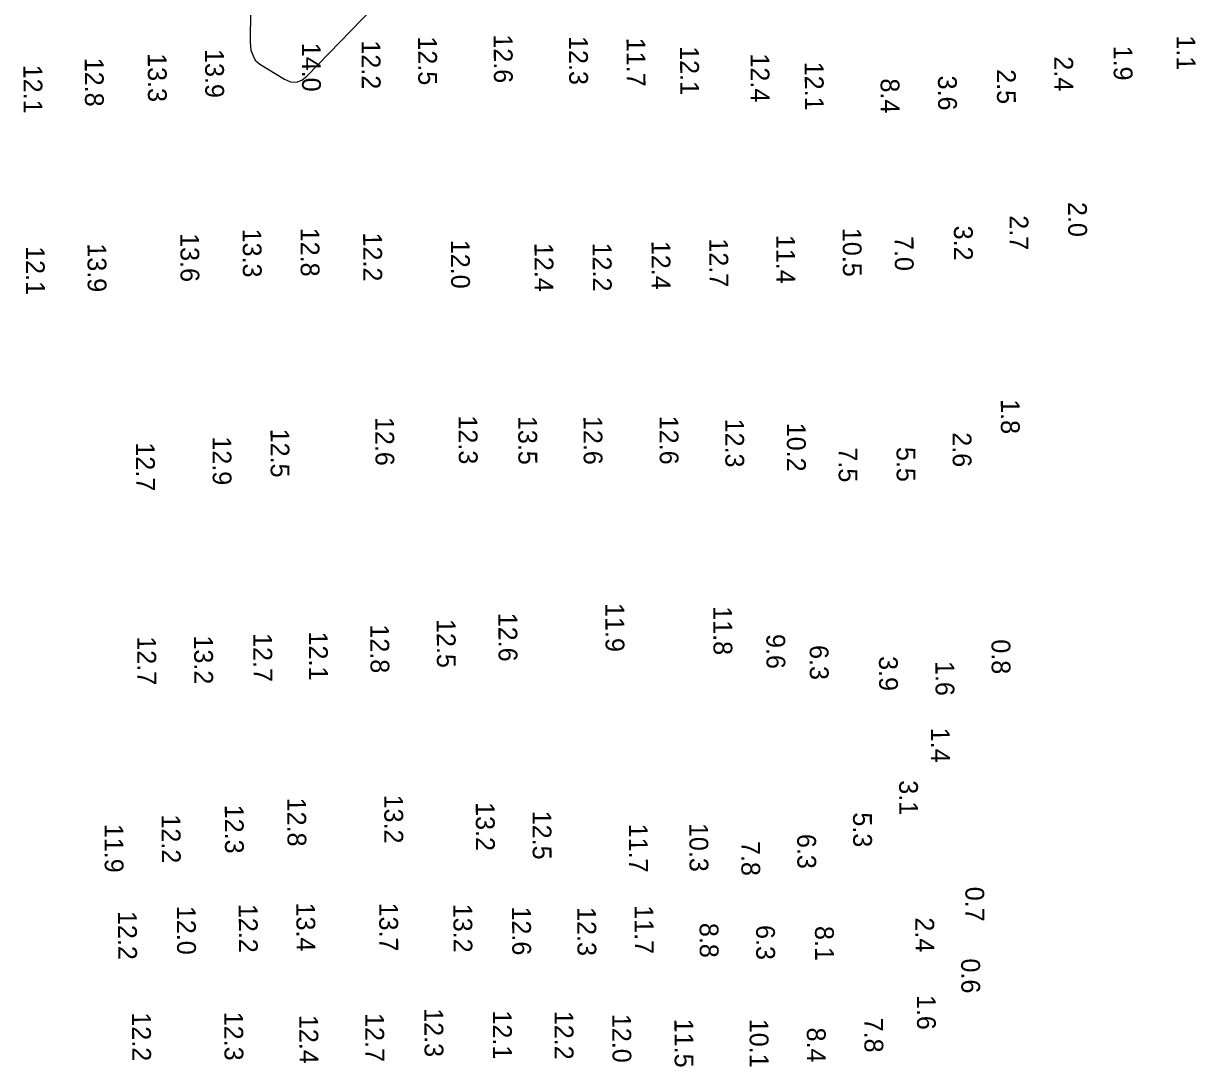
# Model space of a CAD drawing. Extents: x 824616 to 827440, y 158441 to 163197.
# Drawn here: x 824662.7 to 824974.5, y 160870 to 161147.6 of the extents above; entities that cross this region are included whole.
import ezdxf

# ---------------------------------------------------------------- set-up
doc = ezdxf.new("R2010")
doc.units = 0
doc.layers.add('V-CHAN-CONT-EL14', color=7, linetype='Continuous')
doc.layers.add('V-TOPO-SOUN', color=7, linetype='Continuous')

msp = doc.modelspace()

# ---------------------------------------------------------------- linework, layer by layer
at = {"layer": 'V-CHAN-CONT-EL14'}
msp.add_lwpolyline([(824723.12, 161150.99), (824723.05, 161142.63), (824723.24, 161140.44), (824723.87, 161138.92), (824724.37, 161137.81), (824725.63, 161136.77), (824732.2, 161132.77), (824733.8, 161132.07), (824735.33, 161131.96), (824736.78, 161132.45), (824738.15, 161133.53), (824776.31, 161172.97)], dxfattribs=at)

# ---------------------------------------------------------------- texts
at = {"layer": 'V-TOPO-SOUN'}
for s, p in [('12.6 ', (824787.83, 161144.67)), ('12.3 ', (824807.86, 161144.21)), ('1.1', (824969.5, 161144.39)), ('14.0 ', (824736.79, 161142.43)), ('12.2 ', (824752.68, 161143.06)), ('12.5 ', (824767.71, 161144.12)), ('11.7 ', (824823.15, 161143.76)), ('12.1 ', (824837.4, 161141.52)), ('1.9', (824952.73, 161141.66)), ('12.8 ', (824679.04, 161138.43)), ('13.3 ', (824695.8, 161139.66)), ('13.9 ', (824711.04, 161140.75)), ('12.4 ', (824856.14, 161139.59)), ('2.4', (824936.97, 161138.8)), ('12.1 ', (824662.72, 161136.59)), ('12.1 ', (824870.57, 161137.38)), ('2.5', (824921.69, 161135.39)), ('8.4', (824890.75, 161132.93)), ('3.6', (824906.02, 161133.69)), ('2.0', (824940.63, 161100.05)), ('2.7', (824925.05, 161096.52)), ('13.6 ', (824704.46, 161091.76)), ('13.3 ', (824721.04, 161092.96)), ('12.8 ', (824736.43, 161093.2)), ('12.2 ', (824753.09, 161091.92)), ('11.4 ', (824862.98, 161091.31)), ('10.5 ', (824880.66, 161093.16)), ('3.2', (824910.26, 161093.75)), ('12.1 ', (824663.36, 161088.3)), ('13.9 ', (824679.76, 161089.05)), ('12.0 ', (824776.45, 161089.98)), ('12.4 ', (824798.67, 161089.17)), ('12.2 ', (824814.16, 161089.25)), ('12.4 ', (824829.8, 161089.71)), ('12.7 ', (824845.19, 161090.38)), ('7.0', (824894.5, 161090.99)), ('1.8', (824922.73, 161047.58)), ('12.6 ', (824756.32, 161042.85)), ('12.3 ', (824778.49, 161043.25)), ('13.5 ', (824794.34, 161043.12)), ('12.6 ', (824811.71, 161043.12)), ('12.6 ', (824831.94, 161043.17)), ('12.3 ', (824849.4, 161042.4)), ('12.5 ', (824728.44, 161039.72)), ('10.2 ', (824865.81, 161041.29)), ('2.6', (824909.9, 161038.77)), ('12.7 ', (824692.66, 161036.08)), ('12.9 ', (824713.02, 161037.68)), ('5.5', (824894.99, 161034.86)), ('7.5', (824879.56, 161034.74)), ('11.9 ', (824817.53, 160993.32)), ('11.8 ', (824846.24, 160992.48)), ('12.5 ', (824772.67, 160989.07)), ('12.6 ', (824789.07, 160990.74)), ('12.7 ', (824723.88, 160985.33)), ('12.1 ', (824738.66, 160985.74)), ('12.8 ', (824755, 160987.65)), ('9.6', (824860.36, 160985.08)), ('12.7 ', (824693.01, 160984.47)), ('13.2 ', (824708.11, 160984.7)), ('6.3', (824871.89, 160982.14)), ('0.8', (824920.26, 160983.67)), ('3.9', (824890.32, 160979.19)), ('1.6', (824905.34, 160977.91)), ('1.4', (824904.14, 160960.16)), ('3.1', (824895.68, 160946.16)), ('12.8 ', (824732.91, 160941.53)), ('13.2 ', (824758.7, 160942.35)), ('12.3 ', (824716.29, 160939.65)), ('13.2 ', (824783.06, 160940.34)), ('12.2 ', (824699.49, 160937.07)), ('12.5 ', (824798.15, 160938.05)), ('5.3', (824883.42, 160937.62)), ('11.9 ', (824684.29, 160934.57)), ('11.7 ', (824823.79, 160934.61)), ('10.3 ', (824839.87, 160934.81)), ('7.8', (824853.68, 160930)), ('6.3', (824868.57, 160931.88)), ('0.7', (824913.3, 160917.81)), ('13.4 ', (824735.32, 160913.62)), ('13.7 ', (824757.36, 160913.61)), ('12.2 ', (824687.88, 160911.39)), ('12.0 ', (824703.55, 160912.73)), ('12.2 ', (824720, 160913.26)), ('13.2 ', (824777.09, 160913.3)), ('12.6 ', (824792.71, 160912.57)), ('12.3 ', (824810.06, 160912.4)), ('11.7 ', (824825.32, 160912.91)), ('8.8', (824842.61, 160908.2)), ('6.3', (824857.63, 160907.63)), ('8.1', (824873.3, 160907.38)), ('2.4', (824900, 160909.66)), ('0.6', (824912.19, 160898.73)), ('1.6', (824900.41, 160889.04)), ('12.3 ', (824769.38, 160885.5)), ('12.2 ', (824691.61, 160884.41)), ('12.3 ', (824716.16, 160884.56)), ('12.4 ', (824736.12, 160883.72)), ('12.7 ', (824753.65, 160884.2)), ('12.1 ', (824787.61, 160884.9)), ('12.2 ', (824804.01, 160884.8)), ('12.0 ', (824819.38, 160883.99)), ('11.5 ', (824835.91, 160882.7)), ('10.1 ', (824855.89, 160882.68)), ('7.8', (824886.42, 160882.98)), ('8.4', (824871.14, 160880.35))]:
    msp.add_text(s, height=5, rotation=270.3, dxfattribs=at).set_placement(p)

doc.saveas('drawing.dxf')
